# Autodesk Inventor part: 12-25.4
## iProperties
Created: 2006-02
Material: Steel, Mild
Description: Plain Washer
Document SubType Name: Modeling
Standard: ANSI B18.22 M
Designer: Administrator
Standards Organization: ANSI
Language: en-US
Categories: <MemberInstance><Categories><Category DisplayName="Fasteners" InternalName="e4da775c-781d-43d5-af7c-5136215cf5a6" Mnemonic="FSTN"><Category DisplayName="Washers
Density: 1 g/cm^3
Author: Administrator
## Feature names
1. Body [Extrusion]
